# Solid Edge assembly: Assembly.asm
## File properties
Author: Administrator
Template: Normal.asm
Last saved by: Cadcim
Revision: 5
Application: Solid Edge
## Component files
Stock_support_base.par
thrust_bearing.par
adjusting_screw_nut.par
support_adjusting_screw.par
support_roller_bracket.par
stock_support_roller.par
adjusting_nut_handle.par
adjusting_screw_guide.par
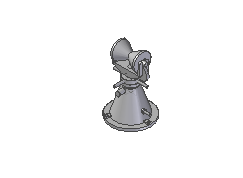
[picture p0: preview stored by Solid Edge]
